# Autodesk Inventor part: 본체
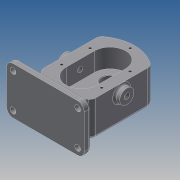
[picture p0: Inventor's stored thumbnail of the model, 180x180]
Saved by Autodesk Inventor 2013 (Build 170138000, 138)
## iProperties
Created: 2019-03
Part Number: 본체
Material: 일반
Document SubType Name: Modeling
Designer: Administrator
Density: 1 g/cm^3
Author: Administrator
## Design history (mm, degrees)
sketch "스케치1"
  geometry: L1 (-40, 44.721)-(-40, -44.721); L2 (40, 44.721)-(40, -44.721); A1 r 60 centre (0, 0) between (40, 44.721) and (-40, 44.721); A2 r 60 centre (0, 0) between (-40, -44.721) and (40, -44.721); 1 further point
  constraints: 4 end point, 4 point on circle, 2 centre point, 1 coincident, 1 vertical
  dimensions: "d1" = 80 distance between parallel lines of L2 L1; "d2" = 40 distance from line of point (0, 0) L2; "d3" = 60 radius of A1; "d4" = 60 radius of A2
extrude "돌출1" new body sketch "스케치1" distance "d5" = 53; taper "d6" = 0 deg
sketch "스케치2"
  geometry: L1 (24, 22)-(24, -22); L2 (-24, 22)-(-24, -22); A1 r 60 centre (0, 0) between (-40, -44.721) and (40, -44.721) reference; A2 r 24 centre (0, 22) between (24, 22) and (-24, 22); A3 r 24 centre (0, -22) between (-24, -22) and (24, -22)
  constraints: 4 end point, 4 point on circle, 2 centre point, 2 tangent, 1 vertical, 1 vertical alignment
  dimensions: "d7" = 48 diameter of A2; "d8" = 48 diameter of A3; "d9" = 44 distance of A3.centre A2.centre; "d10" = 22 distance of A2.centre A1.centre; "d11" = 48 distance between parallel lines of L2 L1
extrude "돌출2" cut sketch "스케치2" distance "d12" = 29; taper "d13" = 0 deg
sketch "스케치4"
  geometry: C1 r 19 at (0, 22); A1 r 60 centre (0, 0) between (40, 44.721) and (-40, 44.721) reference
  constraints: 1 centre point, 1 vertical alignment
  dimensions: "d15" = 38 diameter of C1; "d16" = 22 distance of A1.centre C1.centre
extrude "돌출3" join sketch "스케치4" distance "d17" = 17; taper "d18" = 0 deg
sketch "스케치5"
  geometry: C1 r 19 at (0, 0) reference; 1 further point
hole "구멍1" sketch "스케치5" at (0, 0) diameter "d19" = 17; stored, may be unused: countersink angle "d23" = 90 deg, drill point angle "d25" = 118 deg; dims "d20" = 6, "d21" = 28, "d22" = 7.3, "d24" = 8
sketch "스케치6"
  geometry: C1 r 8.5 at (0, 22) reference; C2 r 12.5 at (0, 22); C3 r 12.5 at (0, -22); A1 r 24 centre (0, 22) between (24, 22) and (-24, 22) reference; A2 r 24 centre (0, -22) between (-24, -22) and (24, -22) reference; 1 further point
  constraints: 2 centre point, 2 coincident
  dimensions: "d26" = 25 diameter of C2; "d27" = 25 diameter of C3
extrude "돌출4" cut sketch "스케치6" distance "d28" = 15; taper "d29" = 0 deg
node "작업 평면1"
sketch "스케치7"
  geometry: L1 (-60, 73)-(60, 73); L2 (60, 73)-(60, 0); L3 (60, 0)-(-60, 0); L4 (-60, 0)-(-60, 73); L5 (-60, 73)-(60, 0); L6 (60, 73)-(-60, 0); L7 (40, 0)-(-40, 0) reference; 2 further points
  constraints: 12 end point, 2 midpoint, 2 parallel, 1 collinear, 1 horizontal, 1 perpendicular
  dimensions: "d31" = 73 distance of L1.end L2.end; "d33" = 120 distance of L1.start L1.end; "d34" = 60 distance from line of point (0, 0) L2
extrude "돌출5" join sketch "스케치7" distance "d35" = 10; taper "d36" = 0 deg
fillet "모깎기1" dims "d37" = 10
fillet "모깎기2" dims "d38" = 3
sketch "스케치10"
  geometry: C1 r 4.5 at (-50, -10); C2 r 4.5 at (50, -10); C3 r 4.5 at (50, -63); C4 r 4.5 at (-50, -63); A1 r 7 centre (-50, -10) between (-50, -3) and (-57, -10) reference; A2 r 7 centre (-50, -63) between (-57, -63) and (-50, -70) reference; A3 r 7 centre (50, -63) between (50, -70) and (57, -63) reference; A4 r 7 centre (50, -10) between (57, -10) and (50, -3) reference; 1 further point
  constraints: 4 centre point, 4 coincident
  dimensions: "d39" = 9 diameter of C1; "d40" = 9 diameter of C2; "d41" = 9 diameter of C3; "d42" = 9 diameter of C4
extrude "돌출6" cut sketch "스케치10" stored distance "d43" = 10; taper "d44" = 0 deg
sketch "스케치12"
  geometry: L1 (50, 0)-(-50, 0) reference; L2 (-6, 0)-(6, 0); L3 (6, 0)-(6, -43); L4 (6, -43)-(-6, -43); L5 (-6, -43)-(-6, 0); 1 further point
  constraints: 8 end point, 2 parallel, 1 horizontal, 1 perpendicular, 1 point on line
  dimensions: "d51" = 43 distance between parallel lines of L1 L4; "d52" = 12 distance between parallel lines of L5 L3; "d53" = 6 distance from line of point (0, 0) L3
extrude "돌출8" join sketch "스케치12" stored distance "d54" = 10; taper "d55" = 0 deg
sketch "스케치13"
  geometry: L1 (-6, 3)-(6, 3) reference; L2 (-6, 3)-(-6, 0) reference; L3 (-6, 0)-(6, 0) reference; L4 (6, 0)-(6, 3) reference; 1 further point
extrude "돌출9" join sketch "스케치13" stored distance "d56" = 10; taper "d57" = 0 deg
sketch "스케치15"
  geometry: A1 r 24 centre (0, 22) between (24, 22) and (-24, 22) reference; A2 r 60 centre (0, 0) between (-40, -44.721) and (40, -44.721) reference; 1 further point
  constraints: 1 vertical alignment
  dimensions: "d68" = 53 distance of A2.centre point (0, 53)
hole "구멍3" sketch "스케치15" at (0, 53) diameter "d69" = 4.134; stored, may be unused: countersink angle "d73" = 90 deg, drill point angle "d75" = 118 deg; dims "d70" = 10, "d71" = 28, "d72" = 7.3, "d74" = 12
chamfer "모따기1" distance "d79" = 0.7; stored, may be unused: second distance "d80" = 2, angle "d81" = 30 deg
chamfer "모따기2" distance "d82" = 1; stored, may be unused: second distance "d83" = 2, angle "d84" = 30 deg
fillet "모깎기3" dims "d85" = 0.5
sketch "스케치17"
  geometry: L1 (-53, 0)-(-53, 89.443) reference; C1 r 11 at (-39, 44.721); 1 further point
  constraints: 1 centre point, 1 horizontal alignment
  dimensions: "d86" = 22 diameter of C1; "d88" = 14 distance from line of L1 C1.centre
extrude "돌출10" join sketch "스케치17" distance "d89" = 8; taper "d90" = 0 deg
sketch "스케치18"
  geometry: C1 r 11 at (0, 0) reference; 1 further point
hole "구멍4" sketch "스케치18" at (0, 0) diameter "d91" = 8.376; stored, may be unused: countersink angle "d95" = 90 deg, drill point angle "d97" = 118 deg; dims "d92" = 30, "d93" = 28, "d94" = 7.3, "d96" = 45
fillet "모깎기4" dims "d98" = 3
fillet "모깎기5" dims "d99" = 3
fillet "모깎기8" dims "d102" = 3
fillet "모깎기9" dims "d103" = 10
fillet "모깎기10" dims "d104" = 3
fillet "모깎기11" dims "d105" = 3
sketch "스케치19"
  geometry: L1 (-60, -10)-(-60, -63) reference; L2 (-50, -73)-(50, -73) reference; 2 further points
  constraints: 1 other
  dimensions: "d106" = 60 distance from line of L1 point (0, -63); "d107" = 10 distance from line of L2 point (0, -63)
feature "엠보싱1" sketch "스케치19" dims "d108" = 0.5, "d109" = 0
node "솔리드1"
pattern_circular "원형 패턴1" dims angle "d77" = 180 deg
mirror "대칭1"
mirror "대칭2"
other parameters: "d30" = -78
